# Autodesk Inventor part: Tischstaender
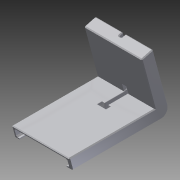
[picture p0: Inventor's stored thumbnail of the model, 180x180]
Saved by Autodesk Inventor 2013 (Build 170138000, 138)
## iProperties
Created: 2013-04
Part Number: Tischstaender
Material: ABS-Kunststoff
Document SubType Name: Modeling
Designer: md
Density: 1 g/cm^3
Author: md
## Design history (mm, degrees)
derived "halteschale.ipt"
  sketch "Vorderseite"
    geometry: L1 (29.467, 53.978)-(29.467, -54.022) reference; L2 (-21.533, 61.978)-(21.467, 61.978) reference; L3 (-29.533, -54.022)-(-29.533, 53.978) reference; L4 (21.467, -62.022)-(-21.533, -62.022) reference; L5 (29.467, 53.978)-(29.467, -54.022) reference; L6 (-21.533, 61.978)-(21.467, 61.978) reference; L7 (-29.533, -54.022)-(-29.533, 53.978) reference; L8 (21.467, -62.022)-(-21.533, -62.022) reference; L9 (-25.533, -44.978)-(25.533, -44.978) reference; L10 (25.533, -44.978)-(25.533, 44.978) reference; L11 (25.533, 44.978)-(-25.533, 44.978) reference; L12 (-25.533, 44.978)-(-25.533, -44.978) reference; L13 (-25.533, -44.978)-(25.533, 44.978) reference; L14 (25.533, -44.978)-(-25.533, 44.978) reference; L15 (-5.533, 49.978)-(5.467, 49.978) reference; L16 (5.467, 49.978)-(5.467, 52.478) reference; L17 (5.467, 52.478)-(-5.533, 52.478) reference; L18 (-5.533, 52.478)-(-5.533, 49.978) reference; L19 (-5.533, 49.978)-(5.467, 52.478) reference; L20 (5.467, 49.978)-(-5.533, 52.478) reference; L21 (-0.033, 61.978)-(-0.033, -62.022) reference; C1 r 5.5 at (-0.033, -53.522) reference; C2 r 1.25 at (-0.033, 56.478) reference; A1 r 8 centre (21.467, 53.978) between (29.467, 53.978) and (21.467, 61.978) reference; A2 r 8 centre (-21.533, 53.978) between (-21.533, 61.978) and (-29.533, 53.978) reference; A3 r 8 centre (-21.533, -54.022) between (-29.533, -54.022) and (-21.533, -62.022) reference; A4 r 8 centre (21.467, -54.022) between (21.467, -62.022) and (29.467, -54.022) reference; A5 r 8 centre (21.467, 53.978) between (29.467, 53.978) and (21.467, 61.978) reference; A6 r 8 centre (-21.533, 53.978) between (-21.533, 61.978) and (-29.533, 53.978) reference; A7 r 8 centre (-21.533, -54.022) between (-29.533, -54.022) and (-21.533, -62.022) reference; A8 r 8 centre (21.467, -54.022) between (21.467, -62.022) and (29.467, -54.022) reference; 3 further points
  sketch "Unterseite"
    geometry: L1 (43, 0)-(43, 7.7) reference; L2 (0, 7.7)-(43, 7.7) reference; L3 (0, 0)-(0, 7.7) reference; L4 (21.467, 0)-(21.5, 7.7) reference; L5 (0, 3.85)-(43, 3.85) reference; L6 (17.25, 2.15)-(25.75, 2.15) reference; L7 (26.25, 2.65)-(26.25, 5.05) reference; L8 (25.75, 5.55)-(17.25, 5.55) reference; L9 (16.75, 5.05)-(16.75, 2.65) reference; L10 (16.75, 2.15)-(26.25, 5.55) reference; L11 (26.25, 2.15)-(16.75, 5.55) reference; C1 r 2.15 at (40.4, 3.85) reference; A1 r 0.5 centre (17.25, 5.05) between (17.25, 5.55) and (16.75, 5.05) reference; A2 r 0.5 centre (25.75, 5.05) between (26.25, 5.05) and (25.75, 5.55) reference; A3 r 0.5 centre (25.75, 2.65) between (25.75, 2.15) and (26.25, 2.65) reference; A4 r 0.5 centre (17.25, 2.65) between (16.75, 2.65) and (17.25, 2.15) reference; 1 further point
sketch "Skizze3"
  geometry: L1 (0, 13.7)-(98, 13.7) reference; L2 (0, 13.7)-(0, 0) reference; L3 (0, 0)-(98, 0) reference; L4 (98, 13.7)-(98, 0) reference; L5 (98, 13.7)-(82.835, 70.296); L6 (82.835, 70.296)-(96.068, 73.842); L7 (96.068, 73.842)-(115.854, 0); L8 (115.854, 0)-(98, 0); L9 (-63.753, 10.313)-(100.895, 54.43); L10 (-61.794, 3)-(0, 3); L11 (0, 3)-(0, 10.838); L12 (0, 10.838)-(-61.794, 10.838); L13 (-61.794, 10.838)-(-61.794, 3); L14 (98, 13.7)-(98, 0); 1 further point
  constraints: 20 end point, 5 perpendicular, 3 parallel, 2 point on line, 1 horizontal
  dimensions: "d5" = 13.7 distance between parallel lines of L1 L3 (derived); "d6" = 13.7 distance between parallel lines of L7 L5 (= d5); "d8" = 15 deg angle of L8 L6; "d9" = 15 deg angle of L1 L9 (derived); "d10" = 20 distance between parallel lines of L6 L9; "d11" = 7.83757 distance between parallel lines of L10 L12
extrude "Bodenplatte" join sketch "Skizze3" distance "d45" = 66 (computed from Halteschale_Arme_Dicke, Grundkoerper_Breite); taper "d46" = 0 deg
sketch "Skizze4"
  geometry: L1 (0, 0)-(-115.854, 0) reference; L2 (0, 0)-(0, 13.7) reference; L3 (0, 13.7)-(-98, 13.7) reference; L4 (-98, 13.7)-(-82.835, 70.296) reference; L5 (-82.835, 70.296)-(-96.068, 73.842) reference; L6 (-96.068, 73.842)-(-115.854, 0) reference; L7 (-113.156, 10.071)-(-96.068, 73.842); L8 (-105.428, 0)-(0, 0); L9 (-82.835, 70.296)-(-97.325, 16.218); L10 (0, 13.7)-(-95.394, 13.7); A1 r 8 centre (-105.428, 8) between (-113.156, 10.071) and (-105.428, 0); A2 r 2 centre (-95.394, 15.7) between (-97.325, 16.218) and (-95.394, 13.7); 1 further point
  constraints: 8 end point, 4 collinear, 4 point on circle, 4 point on line, 4 tangent, 2 centre point
  dimensions: "d48" = 8 radius of A1; "d56" = 2 radius of A2
extrude "Rundung vorne" cut sketch "Skizze4" distance "d57" = 66 (computed from Halteschale_Arme_Dicke, Grundkoerper_Breite); taper "d58" = 0 deg
sketch "Skizze5"
  geometry: L1 (1.9, 0)-(1.9, 7.2) reference; L2 (-1.9, 7.2)-(-1.9, 0) reference; L3 (-1.9, 7.2)-(1.9, 7.2); L4 (1.9, 0)-(1.9, 7.2); L5 (-1.9, 7.2)-(-1.9, 0); A1 r 1.9 centre (0, 0) between (-1.9, 0) and (1.9, 0) reference; 2 further points
  constraints: 6 end point, 2 collinear, 2 tangent, 1 coincident, 1 horizontal alignment, 1 perpendicular, 2 other
extrude "Extrusion3" cut sketch "Skizze5" distance "d61" = 3; taper "d64" = 0 deg
sketch "Skizze6"
  geometry: L1 (34.9, -58.593)-(31.1, -58.593) reference; L2 (34.9, -58.593)-(66, -58.593) reference; L3 (31.1, -52.834)-(31.1, -58.593) reference; L4 (34.9, -58.593)-(34.9, -52.834) reference; L5 (33, -58.593)-(35.5, -58.593); L6 (35.5, -58.593)-(35.5, -50.093); L7 (35.5, -50.093)-(33, -50.093); L8 (33, -50.093)-(33, -58.593); L9 (30.5, -50.093)-(33, -50.093); L10 (30.5, -58.593)-(30.5, -50.093); L11 (33, -58.593)-(30.5, -58.593); 1 further point
  constraints: 14 end point, 2 parallel, 2 symmetric about line, 1 midpoint, 1 perpendicular, 1 point on line
  dimensions: "d65" = 2.5 distance of L5.start L5.end; "d66" = 8.5 distance of L6.end L5.end
extrude "Extrusion4" cut sketch "Skizze6" stored distance "d67" = 3; taper "d68" = 0 deg
sketch "Skizze9"
  geometry: L1 (35.5, -50.093)-(35.5, -58.593) reference; L2 (35.5, -58.593)-(30.5, -58.593) reference; L3 (30.5, -58.593)-(30.5, -50.093) reference; L4 (30.5, -50.093)-(35.5, -50.093) reference; L5 (34.5, -50.093)-(31.5, -50.093); L6 (31.5, -50.093)-(31.5, -36.728); L7 (34.5, -36.728)-(34.5, -50.093); L8 (31.5, -36.728)-(21.5, -36.728); L9 (21.5, -33.728)-(31.5, -33.728); L10 (21.5, -33.728)-(21.5, -23.728); L11 (18.5, -23.728)-(18.5, -33.728); L12 (21.5, -23.728)-(31.5, -23.728); L13 (31.5, -20.728)-(21.5, -20.728); L14 (34.5, -20.728)-(34.5, 0); L15 (34.5, 0)-(31.5, 0); L16 (31.5, 0)-(31.5, -20.728); A1 r 3 centre (31.5, -20.728) between (31.5, -23.728) and (34.5, -20.728); A2 r 3 centre (21.5, -23.728) between (21.5, -20.728) and (18.5, -23.728); A3 r 3 centre (21.5, -33.728) between (18.5, -33.728) and (21.5, -36.728); A4 r 3 centre (31.5, -36.728) between (34.5, -36.728) and (31.5, -33.728); 1 further point
  constraints: 24 end point, 8 point on circle, 7 parallel, 4 centre point, 4 coincident, 2 perpendicular, 2 point on line
  dimensions: "d76" = 3 distance of L5.start L5.end; "d77" = 1 distance between parallel lines of L1 L7 (= -0.5 x d76 + 0.5 x d78); "d78" = 5 distance between parallel lines of L1 L3 (derived)
extrude "Extrusion5" cut sketch "Skizze9" distance "d88" = 5; taper "d89" = 0 deg
fillet "Rundung1" dims "d90" = 1
fillet "Rundung2" dims "d91" = 1
fillet "Rundung3" dims "d92" = 0.5
sketch "Skizze13"
  geometry: L1 (0, 0)-(-105.428, 0) reference; L2 (0, 0)-(0, 13.7) reference; L3 (-98, 13.7)-(-82.835, 70.296) reference; L4 (0, 13.7)-(-3.671, 0); L5 (0, 13.7)-(0, 0); L6 (-3.671, 0)-(0, 0); 1 further point
  constraints: 6 end point, 1 collinear, 1 parallel, 1 perpendicular, 1 point on line
extrude "Extrusion6" cut sketch "Skizze13" stored distance "d127" = 3; taper "d128" = 0 deg
chamfer "Fase1" distance "d93" = 1; stored, may be unused: second distance "d94" = 2, angle "d95" = 45 deg
chamfer "Fase2" distance "d129" = 1; stored, may be unused: second distance "d130" = 2, angle "d131" = 45 deg
fillet "Rundung5" dims "d132" = 8
sketch "Skizze14"
  geometry: L1 (20.429, 10.389)-(32.697, 13.676) reference; L2 (22.241, 3.627)-(20.429, 10.389) reference; L3 (34.508, 6.914)-(22.241, 3.627) reference; L4 (32.697, 13.676)-(34.508, 6.914) reference; L5 (22.5, 2.662)-(34.767, 5.949) reference; L6 (22.5, 2.662)-(34.767, 5.949) reference; L7 (34.767, 5.949)-(22.5, 2.662) reference; L8 (25.5, -4.538)-(34.508, 6.914); L9 (22.241, 3.627)-(25.5, -4.538); L10 (22.241, 3.627)-(34.508, 6.914); 1 further point
  constraints: 6 end point, 1 parallel
extrude "Extrusion7" cut sketch "Skizze14" stored distance "d133" = 3; taper "d134" = 0 deg
fillet "Rundung4" dims "d96" = 0.5
sketch "Pesthoernchen"
  geometry: L1 (60.033, 100.757)-(64, 100.757) reference; L2 (60.033, 48.973)-(60.033, 100.757) reference; L3 (41.967, 44.973)-(56.033, 44.973) reference; L4 (39.967, 34.928)-(39.967, 42.973) reference; L5 (27.967, 30.928)-(35.967, 30.928) reference; L6 (23.967, 42.973)-(23.967, 34.928) reference; L7 (7.967, 44.973)-(21.967, 44.973) reference; L8 (3.967, 100.757)-(3.967, 48.973) reference; L9 (0, 100.757)-(3.967, 100.757) reference; L10 (0, 0)-(0, 100.757) reference; L11 (64, 0)-(0, 0) reference; L12 (64, 100.757)-(64, 0) reference; L13 (34.821, 11.397)-(34.826, 11.582); L14 (34.826, 11.582)-(34.851, 11.716); L15 (34.851, 11.716)-(34.911, 11.818); L16 (34.911, 11.818)-(35.023, 11.905); L17 (35.023, 11.905)-(35.127, 11.958); L18 (35.127, 11.958)-(35.272, 12.017); L19 (35.272, 12.017)-(35.425, 12.066); L20 (35.425, 12.066)-(35.552, 12.085); L21 (35.552, 12.085)-(35.574, 12.085); L22 (35.574, 12.085)-(35.619, 12.07); L23 (35.619, 12.07)-(35.66, 12.028); L24 (35.66, 12.028)-(35.697, 11.966); L25 (35.697, 11.966)-(35.728, 11.891); L26 (35.728, 11.891)-(35.754, 11.809); L27 (35.754, 11.809)-(35.773, 11.727); L28 (35.773, 11.727)-(35.785, 11.652); L29 (35.785, 11.652)-(35.789, 11.59); L30 (35.789, 11.59)-(35.789, 11.16); L31 (35.789, 11.16)-(35.785, 11.061); L32 (35.785, 11.061)-(35.77, 10.979); L33 (35.77, 10.979)-(35.744, 10.912); L34 (35.744, 10.912)-(35.705, 10.859); L35 (35.705, 10.859)-(35.653, 10.82); L36 (35.653, 10.82)-(35.585, 10.793); L37 (35.585, 10.793)-(35.502, 10.778); L38 (35.502, 10.778)-(35.402, 10.773); L39 (35.402, 10.773)-(35.337, 10.773); L40 (35.337, 10.773)-(35.228, 10.778); L41 (35.228, 10.778)-(35.128, 10.794); L42 (35.128, 10.794)-(35.04, 10.822); L43 (35.04, 10.822)-(34.965, 10.863); L44 (34.965, 10.863)-(34.904, 10.919); L45 (34.904, 10.919)-(34.859, 10.989); L46 (34.859, 10.989)-(34.83, 11.077); L47 (34.83, 11.077)-(34.821, 11.181); L48 (34.821, 11.181)-(34.821, 11.397); L49 (33.81, 12.167)-(34.131, 12.124); L50 (34.131, 12.124)-(34.224, 12.068); L51 (34.224, 12.068)-(34.296, 12.027); L52 (34.296, 12.027)-(34.349, 11.991); L53 (34.349, 11.991)-(34.387, 11.951); L54 (34.387, 11.951)-(34.411, 11.894); L55 (34.411, 11.894)-(34.425, 11.812); L56 (34.425, 11.812)-(34.431, 11.693); L57 (34.431, 11.693)-(34.433, 11.526); L58 (34.433, 11.526)-(34.433, 11.246); L59 (34.433, 11.246)-(34.431, 11.121); L60 (34.431, 11.121)-(34.42, 11.009); L61 (34.42, 11.009)-(34.399, 10.913); L62 (34.399, 10.913)-(34.364, 10.834); L63 (34.364, 10.834)-(34.311, 10.773); L64 (34.311, 10.773)-(34.237, 10.733)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; A1 r 4 centre (56.033, 48.973) between (56.033, 44.973) and (60.033, 48.973) reference; A2 r 2 centre (41.967, 42.973) between (41.967, 44.973) and (39.967, 42.973) reference; A3 r 4 centre (35.967, 34.928) between (35.967, 30.928) and (39.967, 34.928) reference; A4 r 4 centre (27.967, 34.928) between (23.967, 34.928) and (27.967, 30.928) reference; A5 r 2 centre (21.967, 42.973) between (23.967, 42.973) and (21.967, 44.973) reference; A6 r 4 centre (7.967, 48.973) between (3.967, 48.973) and (7.967, 44.973) reference; 1 further point
  constraints: 2248 end point
feature "Volumenkörper2::halteschale.ipt" dims "d0" = 10
tag "Bezeichnung1"
node "Projizierte Kontur1"
node "Projizierte Kontur2"
node "Volumenkörper1"
other parameters: "d1" = 3, "d2" = 3, "d4" = 3, "d12" = 75, "d13" = 66, "d14" = 0, "d15" = 1.5, "d16" = 1.5, "d17" = 1.5, "d18" = 7, "d19" = 7, "d20" = 7, "d21" = 3, "d32" = 0, "d47" = 0.75, "d51" = 0, "d53" = 0, "d54" = 3.5, "d55" = -68.5, "d59" = 28.125, "d60" = 62.5, "d62" = 0, "d63" = 5.5, "Halteschale_Arme_Dicke" = 3, "Halteschale_Arme_Freistellung" = 1.5, "d3" = 124, "d22" = 59, "d24" = 124, "d25" = 8, "d26" = 8, "d27" = 8, "d28" = 7.7, "d29" = 0, "d30" = 17, "d31" = 4, "Homebutton_Durchmesser" = 11, "d33" = 8.5, "d34" = 29.5, "d35" = 11, "d36" = 2.5, "d37" = 5, "d38" = 2.5, "d39" = 2.75, "d40" = 9.5, "d41" = 3.4, "d42" = 0.5, "d43" = 4.3, "d44" = 12, "d49" = 1, "Grundkoerper_Breite" = 59, "Grundkoerper_Hoehe" = 124, "Grundkoerper_Dicke" = 7.7, "Grundkoerper_Rundung_Radius" = 8
